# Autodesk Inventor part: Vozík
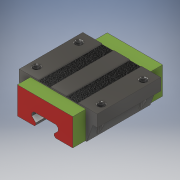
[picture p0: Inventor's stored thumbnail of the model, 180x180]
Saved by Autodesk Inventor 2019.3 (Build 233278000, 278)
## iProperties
Created: 2019-01
Part Number: Vozík
Material: Ocel, uhlík
Document SubType Name: Modeling
Designer: B-hon
Density: 7.85 g/cm^3
Appearance: Ocel – leštěná
Author: B-hon
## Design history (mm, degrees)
sketch "Náčrt1"
  geometry: L1 (-29.5, 18.262)-(29.5, 18.262); L2 (29.5, 18.262)-(29.5, 9.262); L3 (-29.5, 9.262)-(-29.5, 18.262); L4 (-29.5, 18.262)-(29.5, 9.262); L5 (29.5, 18.262)-(-29.5, 9.262); L6 (-21.5, -3.783)-(-26.248, 9.262); L7 (-21.5, -3.783)-(-7.618, -3.783); L8 (21.5, -3.783)-(26.248, 9.262); L9 (21.5, -3.783)-(35.382, -3.783); L10 (29.5, 9.262)-(26.248, 9.262); L11 (-26.248, 9.262)-(-29.5, 9.262); L12 (0, 5.717)-(-8.5, 5.717); L13 (-8.5, 5.717)-(-10, 4.217); L14 (-10, 4.217)-(-10, 2.217); L15 (-10, 2.217)-(-7, -0.783); L16 (-7, -0.783)-(-7, -2.283); L17 (-7, -2.283)-(-8.5, -3.783); L18 (0, 0)-(0, 9.217) reference; L19 (0, 5.717)-(8.5, 5.717); L20 (8.5, 5.717)-(10, 4.217); L21 (10, 4.217)-(10, 2.217); L22 (10, 2.217)-(7, -0.783); L23 (7, -0.783)-(7, -2.283); L24 (7, -2.283)-(8.5, -3.783); L25 (-21.5, -3.783)-(-8.5, -3.783); L26 (8.5, -3.783)-(21.5, -3.783); 3 further points
  constraints: 52 end point, 6 horizontal, 6 symmetric about line, 3 parallel, 3 vertical, 2 equal length, 2 midpoint, 2 perpendicular, 1 point on line, 1 vertical alignment
  dimensions: "d0" = 59 distance of L2.end L3.start; "d1" = 9 distance of L1.end L2.end; "d3" = 43 distance of L6.start L8.start; "d4" = 21.5 horizontal distance of L18.start L6.start (= 0.5 x d3); "d5" = 110 deg angle of L7 L6; "d6" = 70 deg angle of L9 L8; "d7" = 8.5 distance of L12.start L12.end; "d8" = 135 deg angle of L13 L12; "d9" = 1.5 horizontal distance of L12.end L13.end; "d10" = 2 distance of L13.end L14.end; "d11" = 90 deg angle of L17 L15; "d12" = 135 deg angle of L14 L15; "d13" = 7 distance from line of L12.start L16; "d14" = 1.5 distance of L15.end L16.end
extrude "Vysunutí1" new body sketch "Náčrt1" distance "d18" = 48.1; taper "d19" = 0 deg
sketch "Náčrt2"
  geometry: L1 (14.5, -78.425)-(23.5, -78.425); L2 (23.5, -78.425)-(23.5, 5.242); L3 (23.5, 5.242)-(14.5, 5.242); L4 (14.5, 5.242)-(14.5, -78.425); L5 (14.5, -78.425)-(23.5, 5.242); L6 (23.5, -78.425)-(14.5, 5.242); L7 (35.5, -85.613)-(44.5, -85.613); L8 (44.5, -85.613)-(44.5, 6.242); L9 (44.5, 6.242)-(35.5, 6.242); L10 (35.5, 6.242)-(35.5, -85.613); L11 (35.5, -85.613)-(44.5, 6.242); L12 (44.5, -85.613)-(35.5, 6.242); 3 further points
  constraints: 24 end point, 4 midpoint, 4 parallel, 2 horizontal, 2 perpendicular
  dimensions: "d20" = 9 distance of L2.end L3.end; "d21" = 9 distance of L8.end L9.end (= d20); "d22" = 6 distance from line of point (29.5, 0) L2; "d23" = 6 distance from line of L10 point (29.5, 0)
extrude "Vysunutí2" cut sketch "Náčrt2" distance "d24" = 0.5; taper "d25" = 0 deg
sketch "Náčrt3"
  geometry: L1 (-6, 18.262)-(-6, 17.762) reference; L2 (-6, 17.762)-(-15, 17.762) reference; L3 (-15, 17.762)-(-15, 18.262) reference; L4 (-15, 18.262)-(-29.5, 18.262) reference; L5 (-29.5, 18.262)-(-29.5, 9.262) reference; L6 (-29.5, 9.262)-(-26.248, 9.262) reference; L7 (-26.248, 9.262)-(-21.5, -3.783) reference; L8 (-21.5, -3.783)-(-8.5, -3.783) reference; L9 (-8.5, -3.783)-(-7, -2.283) reference; L10 (-7, -2.283)-(-7, -0.783) reference; L11 (-7, -0.783)-(-10, 2.217) reference; L12 (-10, 2.217)-(-10, 4.217) reference; L13 (-10, 4.217)-(-8.5, 5.717) reference; L14 (-8.5, 5.717)-(8.5, 5.717) reference; L15 (8.5, 5.717)-(10, 4.217) reference; L16 (10, 4.217)-(10, 2.217) reference; L17 (10, 2.217)-(7, -0.783) reference; L18 (7, -0.783)-(7, -2.283) reference; L19 (7, -2.283)-(8.5, -3.783) reference; L20 (8.5, -3.783)-(21.5, -3.783) reference; L21 (21.5, -3.783)-(26.248, 9.262) reference; L22 (26.248, 9.262)-(29.5, 9.262) reference; L23 (29.5, 9.262)-(29.5, 18.262) reference; L24 (29.5, 18.262)-(15, 18.262) reference; L25 (15, 18.262)-(15, 17.762) reference; L26 (15, 17.762)-(6, 17.762) reference; L27 (6, 17.762)-(6, 18.262) reference; L28 (6, 18.262)-(-6, 18.262) reference; L29 (21, -3.283)-(21, 17.262); L30 (21, 17.262)-(-21, 17.262); L31 (-21, 17.262)-(-21, -3.283); L32 (-21, -3.283)-(-8, -3.283); L33 (8, -3.283)-(21, -3.283); 1 further point
  constraints: 10 end point, 3 parallel, 2 horizontal, 2 perpendicular, 2 point on line
  dimensions: "d26" = 0.5 distance between parallel lines of L30 L2; "d28" = 0.5 distance from line of L7.end L31; "d29" = 0.5 horizontal distance of L20.end L29.start
extrude "Vysunutí3" join sketch "Náčrt3" distance "d30" = 10; taper "d31" = 0 deg
sketch "Náčrt4"
  geometry: L1 (6, 17.762)-(6, 18.262) reference; L2 (6, 18.262)-(-6, 18.262) reference; L3 (-6, 18.262)-(-6, 17.762) reference; L4 (-6, 17.762)-(-15, 17.762) reference; L5 (-15, 17.762)-(-15, 18.262) reference; L6 (-15, 18.262)-(-29.5, 18.262) reference; L7 (-29.5, 18.262)-(-29.5, 9.262) reference; L8 (-29.5, 9.262)-(-26.248, 9.262) reference; L9 (-26.248, 9.262)-(-21.5, -3.783) reference; L10 (-21.5, -3.783)-(-8.5, -3.783) reference; L11 (-8.5, -3.783)-(-7, -2.283) reference; L12 (-7, -2.283)-(-7, -0.783) reference; L13 (-7, -0.783)-(-10, 2.217) reference; L14 (-10, 2.217)-(-10, 4.217) reference; L15 (-10, 4.217)-(-8.5, 5.717) reference; L16 (-8.5, 5.717)-(8.5, 5.717) reference; L17 (8.5, 5.717)-(10, 4.217) reference; L18 (10, 4.217)-(10, 2.217) reference; L19 (10, 2.217)-(7, -0.783) reference; L20 (7, -0.783)-(7, -2.283) reference; L21 (7, -2.283)-(8.5, -3.783) reference; L22 (8.5, -3.783)-(21.5, -3.783) reference; L23 (21.5, -3.783)-(26.248, 9.262) reference; L24 (26.248, 9.262)-(29.5, 9.262) reference; L25 (29.5, 9.262)-(29.5, 18.262) reference; L26 (29.5, 18.262)-(15, 18.262) reference; L27 (15, 18.262)-(15, 17.762) reference; L28 (15, 17.762)-(6, 17.762) reference; L29 (-21, 17.262)-(21, 17.262); L30 (21, 17.262)-(21, -3.283); L31 (-21, -3.283)-(-21, 17.262); L32 (21, -3.283)-(8, -3.283); L33 (-8, -3.283)-(-21, -3.283); 1 further point
  constraints: 10 end point, 3 parallel, 2 point on line, 1 horizontal, 1 perpendicular
  dimensions: "d32" = 0.5 distance between parallel lines of L4 L29; "d34" = 0.5 distance from line of L9.end L31; "d35" = 0.5 distance from line of L22.end L30
extrude "Vysunutí4" join sketch "Náčrt4" distance "d36" = 10; taper "d37" = 0 deg
sketch "Náčrt5"
  geometry: L1 (44.5, 48.1)-(59, 48.1) reference; L2 (0, 48.1)-(0, 0) reference; 5 further points
  constraints: 2 horizontal alignment, 2 vertical alignment
  dimensions: "d38" = 32 distance of point (54, 8.05) point (54, 40.05); "d39" = 8.05 distance from line of L1 point (54, 40.05) (computed from d38); "d40" = 49 distance of point (5, 40.05) point (54, 40.05); "d41" = 5 distance from line of L2 point (5, 40.05)
hole "Díra1" sketch "Náčrt5" at (54, 40.05), (54, 8.05), (5, 40.05), (5, 8.05) diameter "d42" = 4.917; stored, may be unused: countersink angle "d46" = 90 deg, drill point angle "d48" = 0 deg; dims "d43" = 9, "d44" = 6, "d45" = 8, "d47" = 8
node "Těleso1"
node "Promítnutá smyčka1"
node "Promítnutá smyčka2"
other parameters: "d2" = 13, "d27" = 0.5, "d33" = 0.5
